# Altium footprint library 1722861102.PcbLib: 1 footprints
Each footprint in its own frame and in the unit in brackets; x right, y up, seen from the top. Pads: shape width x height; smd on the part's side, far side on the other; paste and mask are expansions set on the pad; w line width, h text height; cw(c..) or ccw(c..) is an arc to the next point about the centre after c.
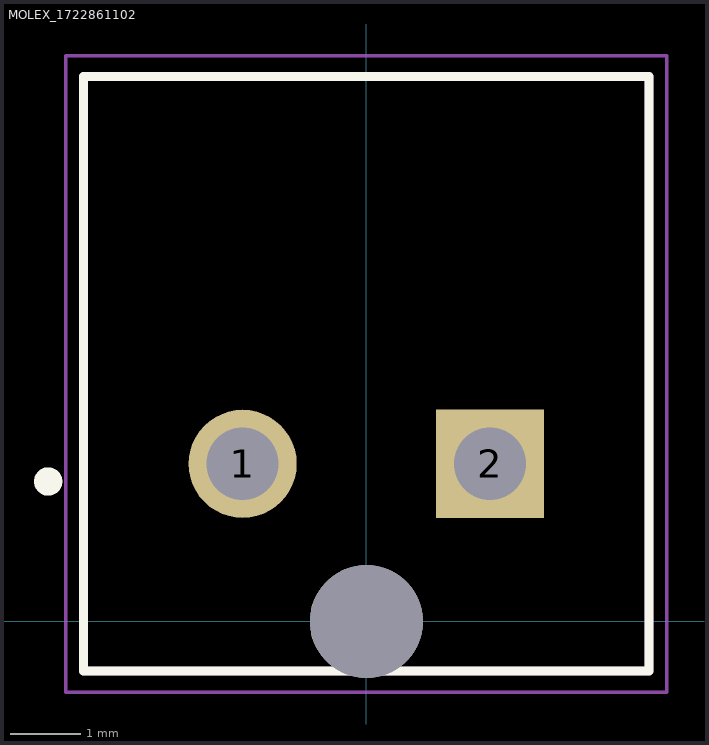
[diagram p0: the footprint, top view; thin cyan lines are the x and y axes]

## MOLEX_1722861102 [mm]
pads (3):
  round 1.53 hole 1.02: 1(-1.75,2.23)
  rect 1.53x1.53 hole 1.02: 2(1.75,2.23)
  round 1.6 hole 1.6 unplated: ""(0,0)
Top Overlay:
  circle w0.2: c-4.5,1.98 r0.1
  lines w0.127: -4,-0.7 -4,7.71 4,7.71 4,-0.7 -4,-0.7
Mechanical 13:
  lines w0.127: -4,-0.7 -4,7.71 4,7.71 4,-0.7 -4,-0.7
Mechanical 15:
  lines w0.05: -4.25,-1 4.25,-1 4.25,8 -4.25,8 -4.25,-1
